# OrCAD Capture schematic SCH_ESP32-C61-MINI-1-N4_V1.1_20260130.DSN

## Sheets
1 01_DesignBlock: title: ESP32-C61-MINI-1-N4; rev: V1.1; note: <01_DesignBlock>
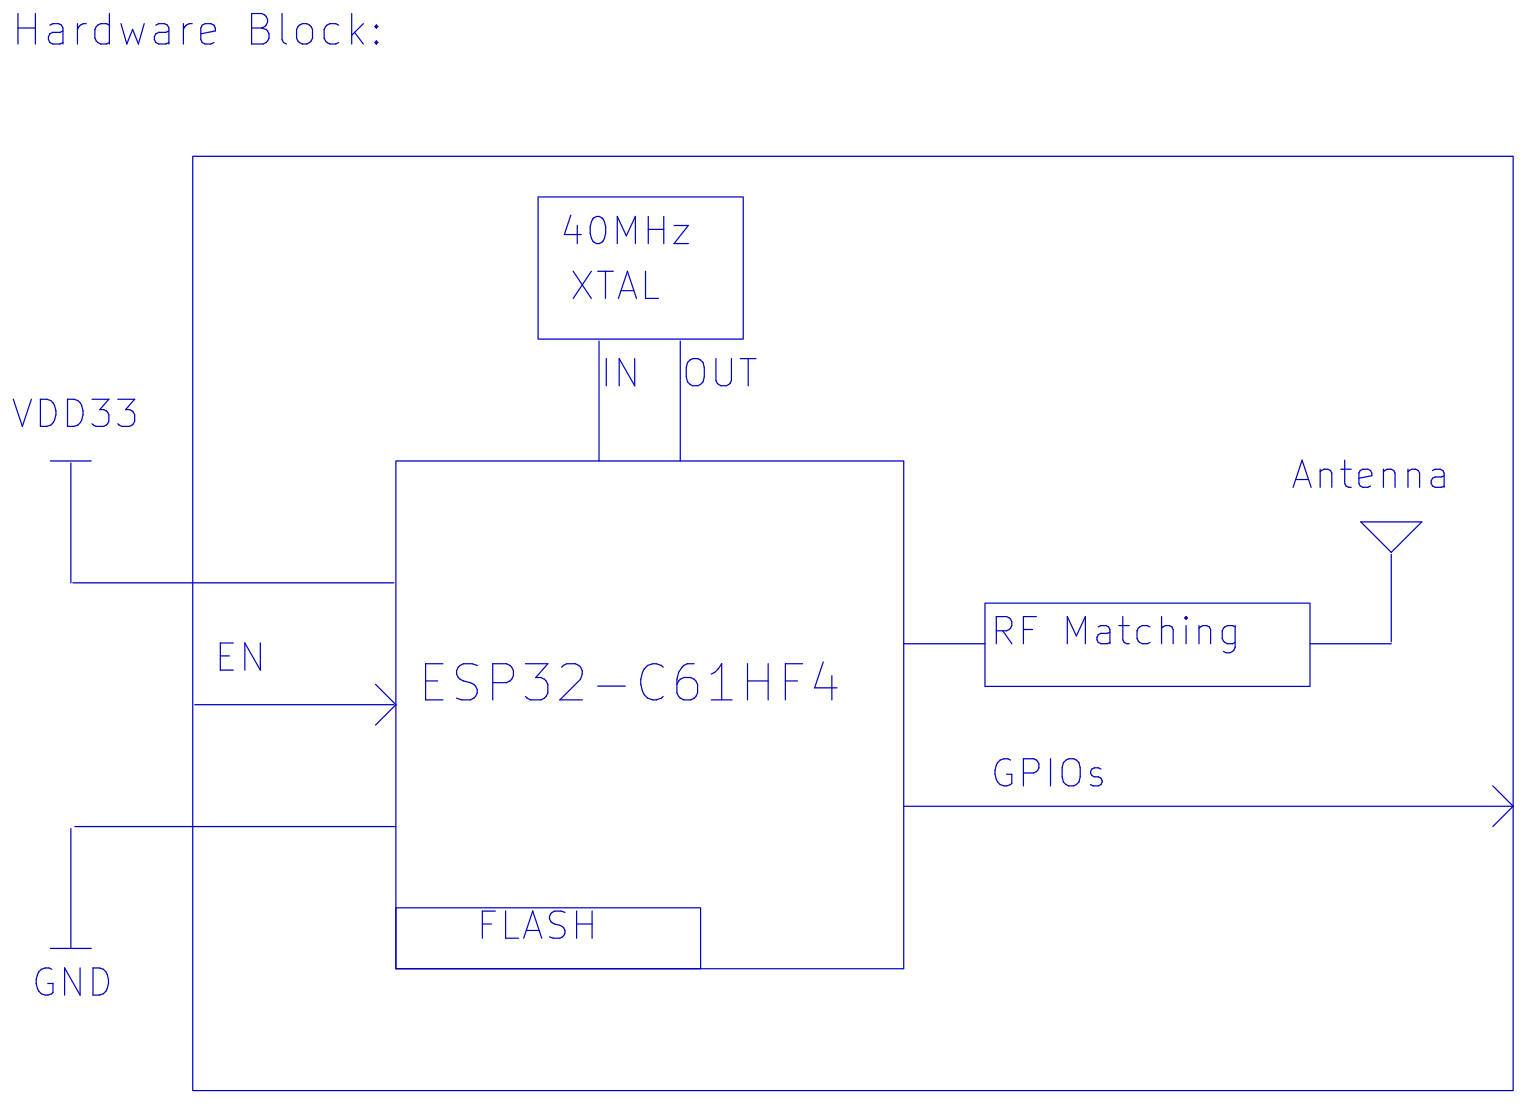
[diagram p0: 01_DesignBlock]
2 02_ESP32-C61-MINI-1-N4: size A4; title: <ESP32-C61-MINI-1-N4>; note: <02_ESP32-C61-MINI-1-N4>
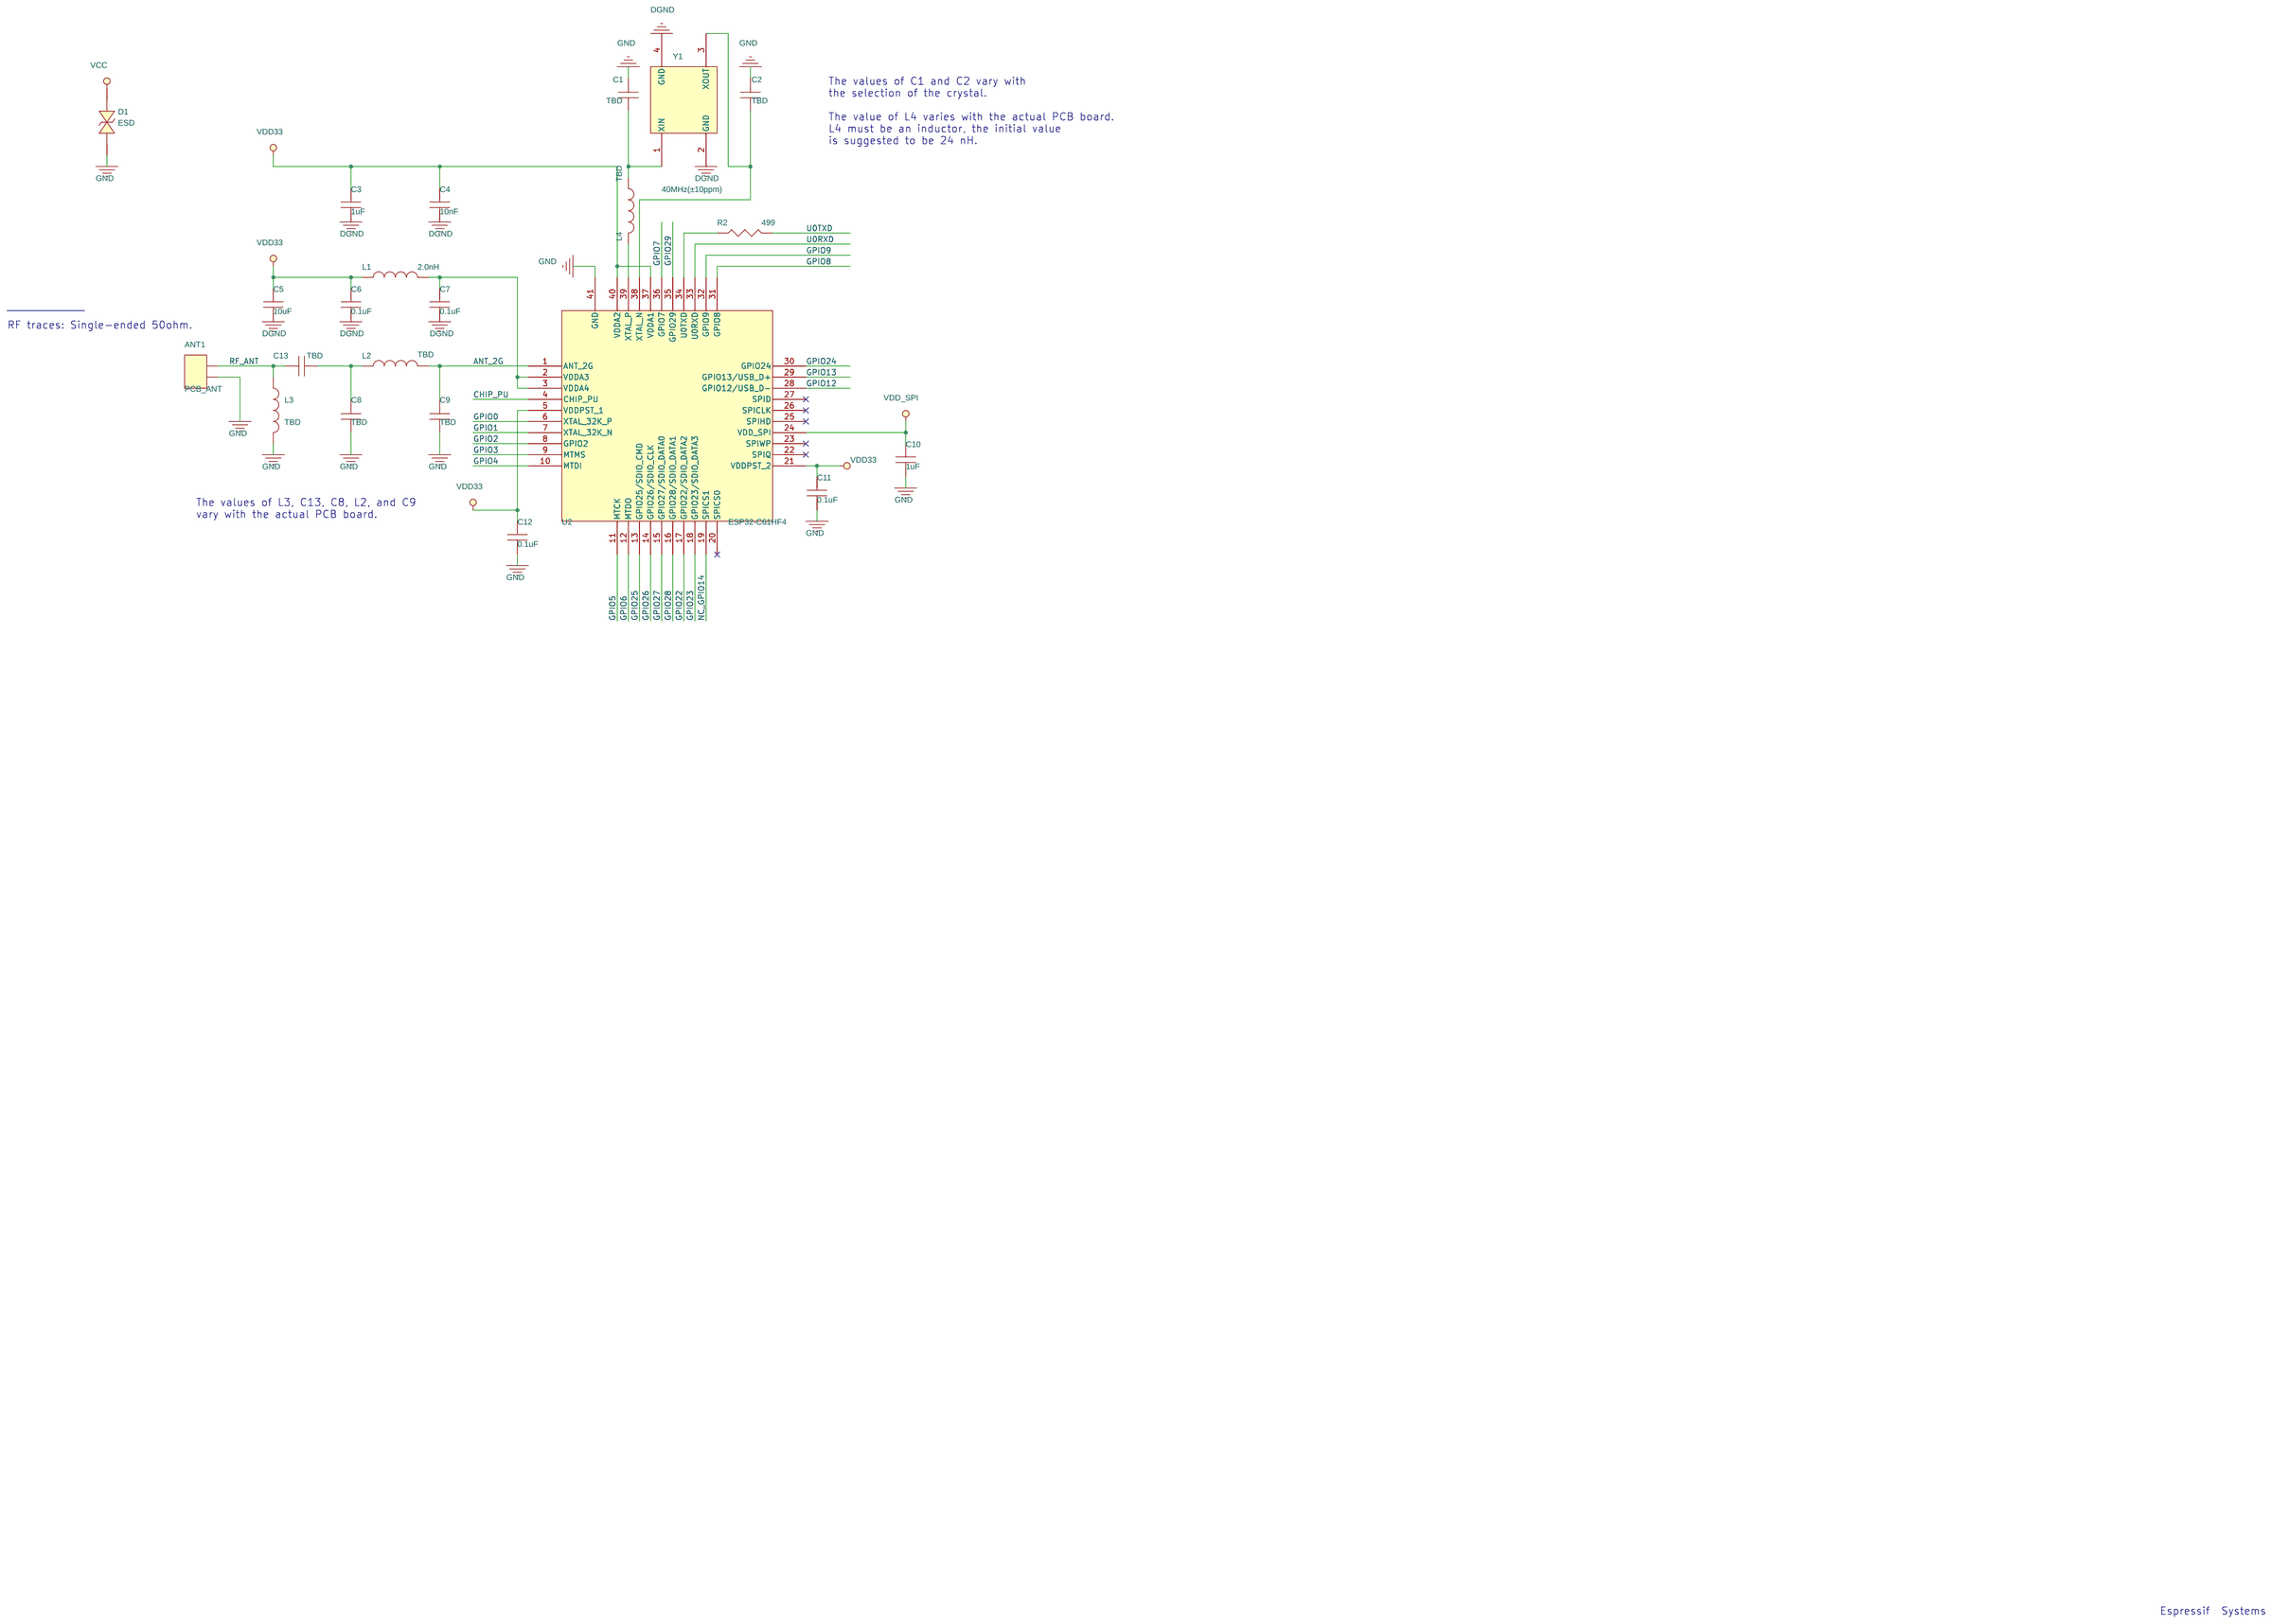
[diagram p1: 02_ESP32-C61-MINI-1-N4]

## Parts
ANT1  PCB_ANT  [MINI-ANT-TYPED-H]
C1  TBD  [C0201]
C2  TBD  [C0201]
C3  1uF  [C0201]
C4  10nF  [C0201]
C5  10uF  [C0402]
C6  0.1uF  [C0201]
C7  0.1uF  [C0201]
C8  TBD  [C0201]
C9  TBD  [C0201]
C10  1uF  [C0201]
C11  0.1uF  [C0201]
C12  0.1uF  [C0201]
C13  TBD  [C0201]
D1  ESD  [SOD882]
L1  2.0nH  [L0201]
L2  TBD  [L0201]
L3  TBD  [L0201]
L4  TBD  [L0201]
R2  499  [R0201]
U2  ESP32-C61HF4  [QFN40_0P4_5_E3P3X3P2]
Y1  40MHz(±10ppm)  [XTAL2016]

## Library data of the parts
ANT1 = PCB_ANT
C1 C2 C8 C9 C13 = CAP
C3 C10 = CAPACITOR: CODE12: ES01.1.1.105.2.7.1.00; Part Number: ES01111052710000; Part Type: Capacitor
C4 = CAPACITOR: CODE12: ES01.1.1.103.3.6.2.00; Part Number: ES01111033620000; Part Type: Capacitor
C5 = CAPACITOR: CODE12: ES01.1.2.106.2.7.1.00; Part Number: ES01121062710000; Part Type: Capacitor
C6 C7 C11 C12 = CAPACITOR: CODE12: ES01.1.1.104.2.6.1.00; Part Number: ES01111042610000; Part Type: Capacitor
D1 = DIODE_BI_DIR: CODE12: ES06.1.1.3.01.00000; Part Number: ES06113010000000; Part Type: Diode
L1 = INDUCTOR: CODE12: ES02.1.1.2N0.0.2.001; Part Number: ES02112N00200100; Part Type: Inductor
L2-L4 = Inductor
R2 = RESISTOR: CODE12: ES03.1.1.4990.1.000; Part Number: ES03114990100000; Part Type: Resistor
U2 = ESP32-C61-QFN40_2: CODE12: ES00.11.A.N.N.N.2.000; Part Number: ES0011ANNN200000; Part Type: ESP ICs
Y1 = XTAL_4P: CODE12: ES04.1.4.4002.0.2.01; Part Number: ES04144002020100; Part Type: Clock

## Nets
GND: ANT1.2 C1.2 C2.2 C3.2 C4.2 C5.2 C6.2 C7.2 C8.1 C9.1 C10.2 C11.2 C12.2 D1.2 L3.1 U2.41(GND) Y1.2(GND) Y1.4(GND)
VDD33: C3.1 C4.1 C5.1 C6.1 C11.1 C12.1 D1.1 L1.1 U2.5(VDDPST_1) U2.21(VDDPST_2) U2.37(VDDA1) U2.40(VDDA2)
VDD_SPI: C10.1 U2.24(VDD_SPI)
ANT_2G: C9.2 L2.1 U2.1(ANT_2G)
CHIP_PU: U2.4(CHIP_PU)
GPIO0: U2.6(XTAL_32K_P)
GPIO1: U2.7(XTAL_32K_N)
GPIO2: U2.8(GPIO2)
GPIO3: U2.9(MTMS)
GPIO4: U2.10(MTDI)
GPIO5: U2.11(MTCK)
GPIO6: U2.12(MTDO)
GPIO7: U2.36(GPIO7)
GPIO8: U2.31(GPIO8)
GPIO9: U2.32(GPIO9)
GPIO12: U2.28(GPIO12/USB_D-)
GPIO13: U2.29(GPIO13/USB_D+)
GPIO22: U2.17(GPIO22/SDIO_DATA2)
GPIO23: U2.18(GPIO23/SDIO_DATA3)
GPIO24: U2.30(GPIO24)
GPIO25: U2.13(GPIO25/SDIO_CMD)
GPIO26: U2.14(GPIO26/SDIO_CLK)
GPIO27: U2.15(GPIO27/SDIO_DATA0)
GPIO28: U2.16(GPIO28/SDIO_DATA1)
GPIO29: U2.35(GPIO29)
NC_GPIO14: U2.19(SPICS1)
RF_ANT: ANT1.1 C13.2 L3.2
U0RXD: U2.33(U0RXD)
U0TXD: R2.2
N16985797: C2.1 U2.38(XTAL_N) Y1.3(XOUT)
N16985859: C7.1 L1.2 U2.2(VDDA3) U2.3(VDDA4)
N16986042: R2.1 U2.34(U0TXD)
N16986053: C1.1 L4.2 Y1.1(XIN)
N17016143: L4.1 U2.39(XTAL_P)
N17028792: C8.2 C13.1 L2.2

Not connected (* = marked no-connect by the designer): U2 20(SPICS0)* 22(SPIQ)* 23(SPIWP)* 25(SPIHD)* 26(SPICLK)* 27(SPID)*

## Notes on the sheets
sheet 1
- Hardware Block:
- 40MHz
- XTAL
- IN
- OUT
- VDD33
- Antenna
- RF Matching
- EN
- ESP32-C61HF4
- GPIOs
- FLASH
- GND
sheet 2
- The values of C1 and C2 vary with
  the selection of the crystal.
  The value of L4 varies with the actual PCB board.
  L4 must be an inductor, the initial value
  is suggested to be 24 nH.
- RF traces: Single-ended 50ohm.
- The values of L3, C13, C8, L2, and C9
  vary with the actual PCB board.
- Espressif  Systems
